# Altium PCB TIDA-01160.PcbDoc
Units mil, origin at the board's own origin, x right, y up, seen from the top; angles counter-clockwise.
Board outline 1299.21 x 905.51 mil, 2 copper layers (Top Layer, Bottom Layer), stack 62 mil thick; 52 components, 24 nets, 111 pads, 30 vias.
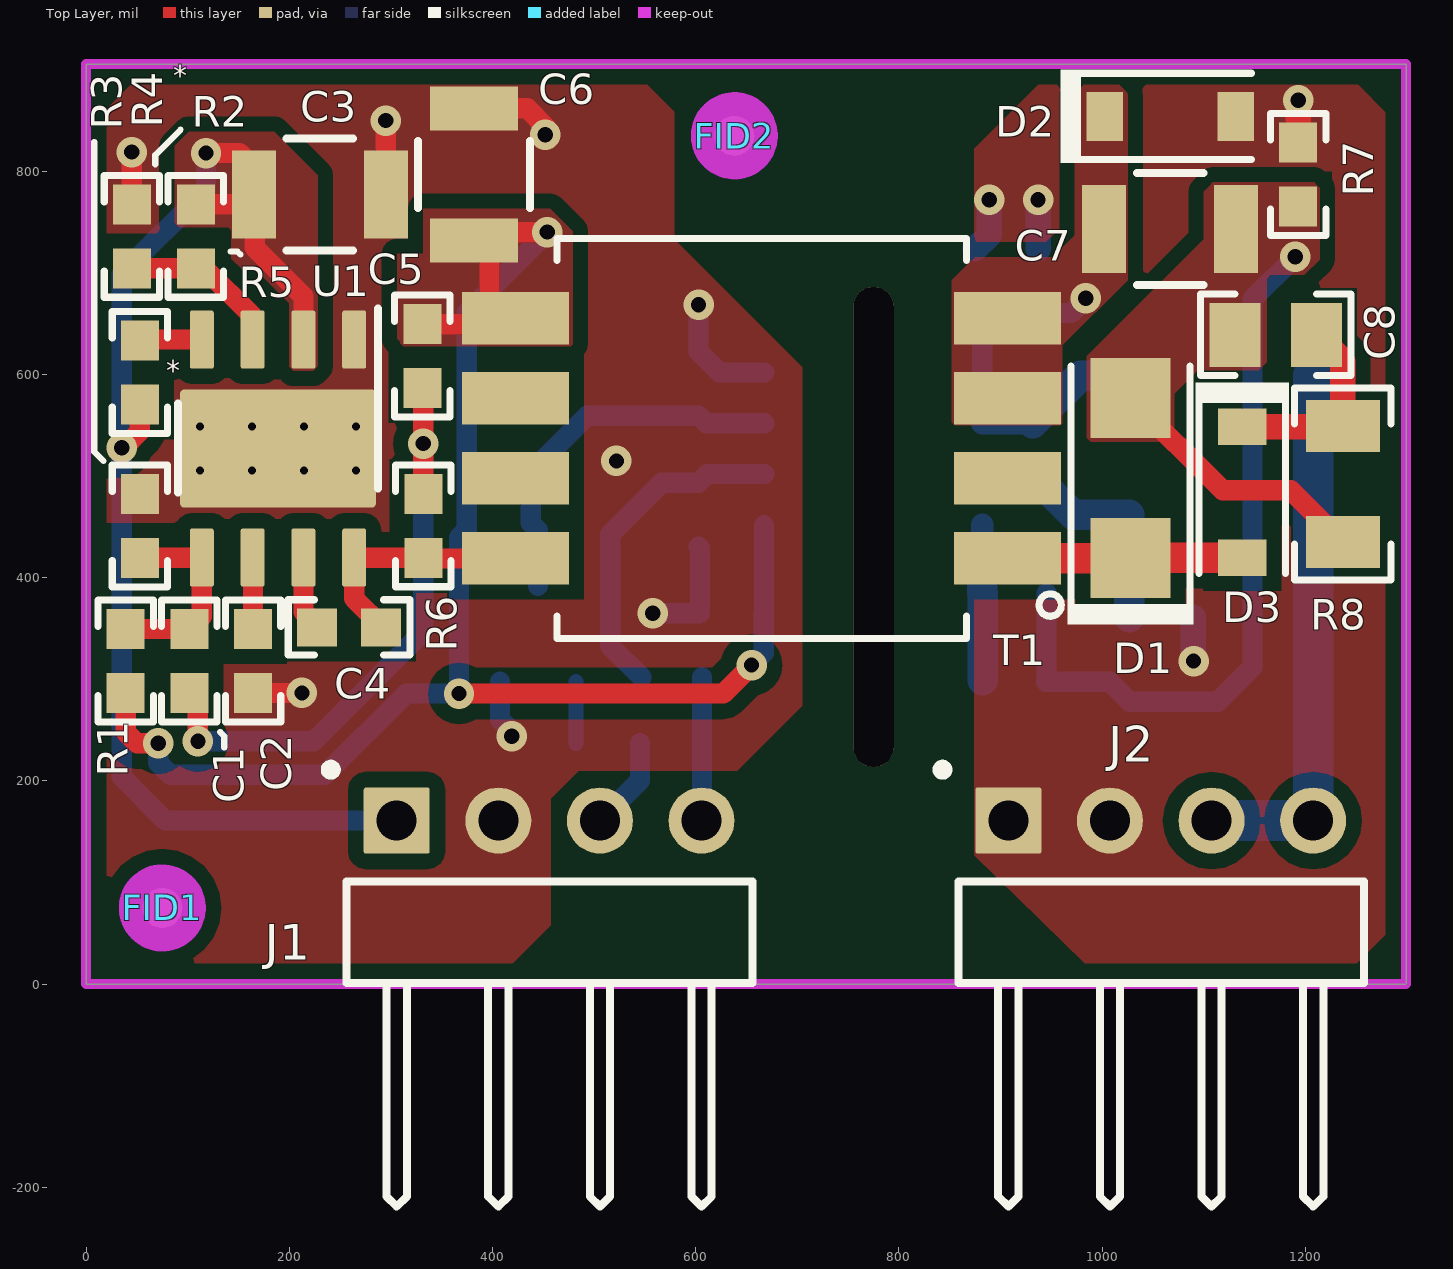
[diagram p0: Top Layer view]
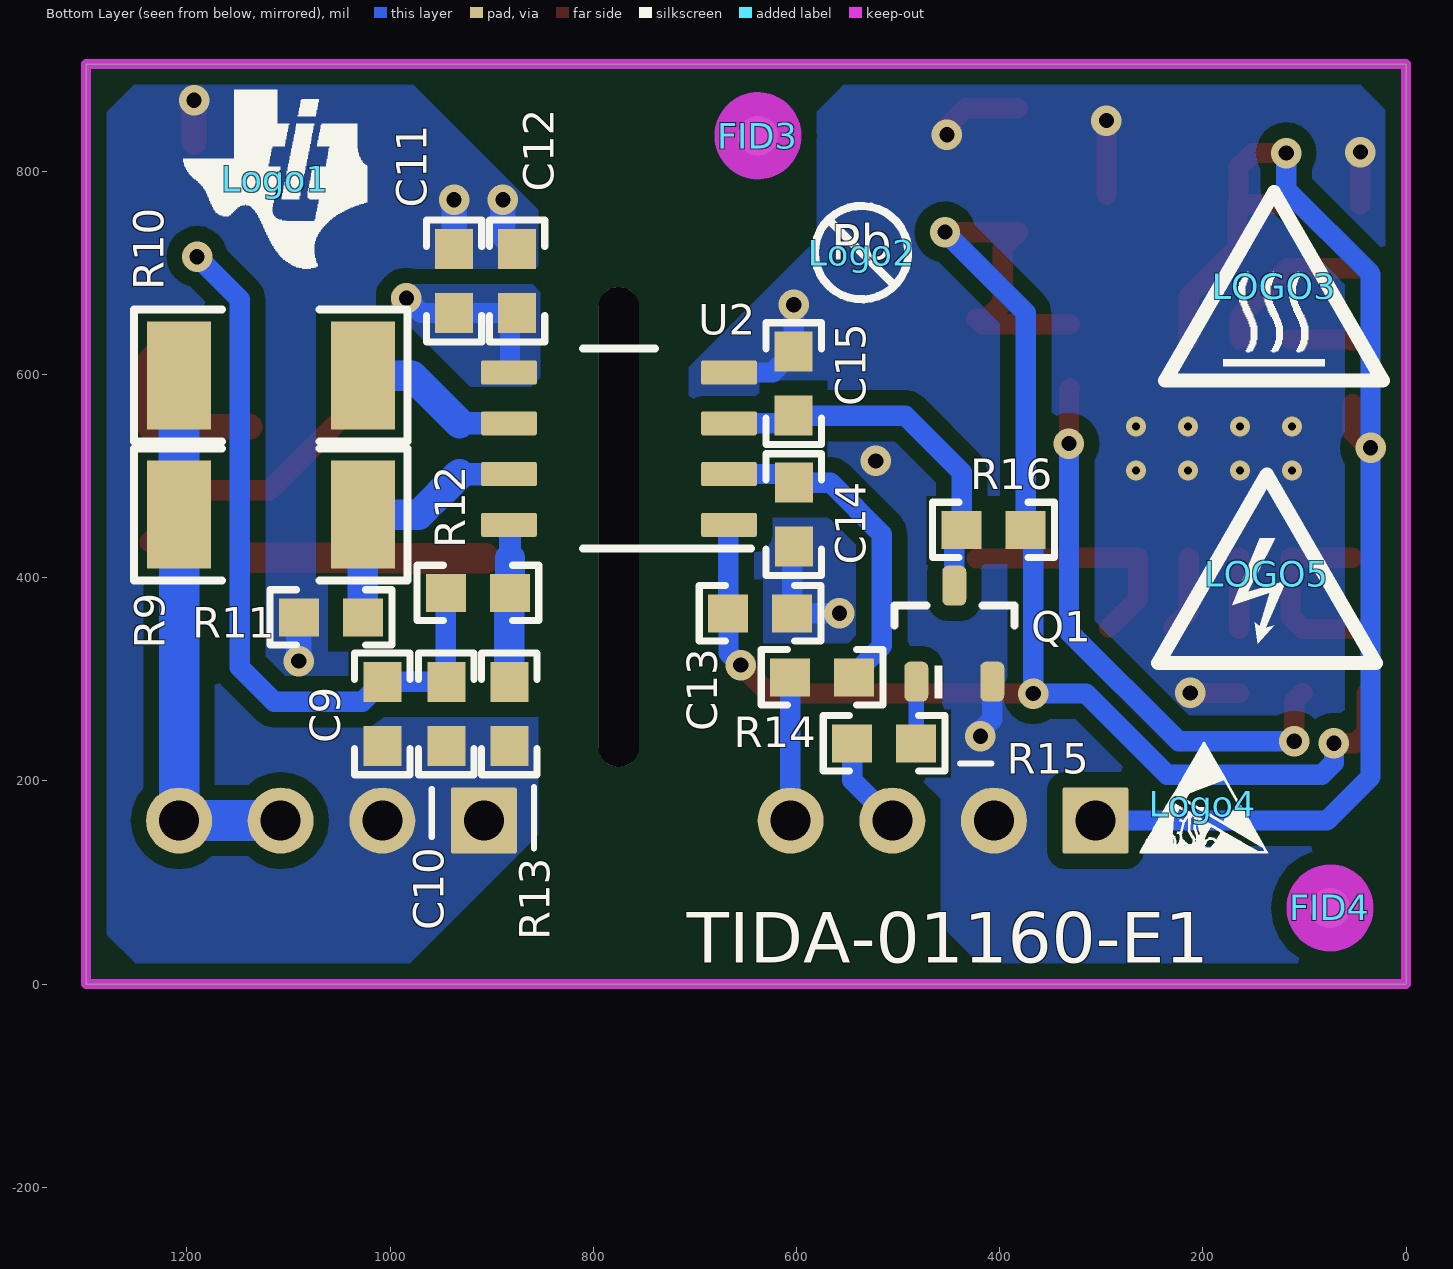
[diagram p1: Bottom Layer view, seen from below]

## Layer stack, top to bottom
Top Solder: solder mask 0.4, Solder Resist, Dk 3.5
Top Layer: signal copper 1.4
Dielectric1: core 59.2, FR-4 High Tg, Dk 4.8
Bottom Layer: signal copper 1.4
Bottom Solder: solder mask 0.4, Solder Resist, Dk 3.5

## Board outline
0,0 0,905.51 1299.21,905.51 1299.21,0

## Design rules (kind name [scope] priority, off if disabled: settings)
AcuteAngle [All] p1: minimum=4.50000000000000E+0001 checktracksonly=FALSE
AssemblyTestPointUsage [All] p1: valid=2
Clearance Clearance_Keepouts [((IsTrack Or IsArc) And Not InPoly) And IsFree and IsKeepOut vs ((IsTrack Or IsArc) And Not InPoly) And IsFree and IsKeepOut] p1: gap=15
Clearance Clearance_BoardEdge_MountingHoles [OnCopper and InComponentClass('Mounting Holes') vs IsKeepOut] p2: gap=40
Clearance Clearance_BoardEdge_Poly [OnCopper and InPoly vs IsKeepOut] p3: gap=15
Clearance Clearance_BoardEdge [OnCopper and Not InComponentClass('Logo') and not InComponentClass('FiducialMark') and not InRegion(1000,500,4000,800) and Not IsKeepout vs IsKeepOut] p4: gap=15
Clearance Clearance_Poly [InPolygon] p5: gap=15
Clearance [All] p6: gap=7.87
ComponentClearance ComponentClearance_MountingHoles_FiducialMarks [InComponentClass('Mounting Holes') vs InComponentClass('FiducialMark')] p1: gap=50 collisioncheckmode=3 verticalgap=10 showdistances=FALSE
ComponentClearance ComponentClearance_Shunt [InComponentClass('Header') vs InComponentClass('Shunt')] p2: gap=0 collisioncheckmode=3 verticalgap=0 showdistances=FALSE
ComponentClearance ComponentClearance_Logo [InComponentClass('Logo')] p3: gap=10 collisioncheckmode=3 verticalgap=10 showdistances=FALSE
ComponentClearance ComponentClearance_ScrewToNut [(HasFootprint('NY PMS 440 0025 PH')) vs (HasFootprint('Keystone_1902C'))] p4: gap=5 collisioncheckmode=3 verticalgap=10 showdistances=FALSE
ComponentClearance ComponentClearance_MountingHoles [InComponentClass('Mounting Holes')] p5: gap=200 collisioncheckmode=3 verticalgap=100000 showdistances=FALSE
ComponentClearance ComponentClearance_SmallPassives [HasFootprint('0201*') or HasFootprint('0402*') or HasFootprint('0508') or HasFootprint('0603*') or HasFootprint('0612') or HasFootprint('0805*') or HasFootprint('0815*') or HasFootprint('0830*') or HasFootprint('1206*') or HasFootprint('1210*') or HasFootprint('1808*') or HasFootprint('1812*') or HasFootprint('1825*') or HasFootprint('2010*') or HasFootprint('2220*') or HasFootprint('2225*') or HasFootprint('2512*') or HasFootprint('2728*') or HasFootprint('3518*') vs HasFootprint('0201*') or HasFootprint('0402*') or HasFootprint('0508') or HasFootprint('0603*') or HasFootprint('0612') or HasFootprint('0805*') or HasFootprint('0815*') or HasFootprint('0830*') or HasFootprint('1206*') or HasFootprint('1210*') or HasFootprint('1808*') or HasFootprint('1812*') or HasFootprint('1825*') or HasFootprint('2010*') or HasFootprint('2220*') or HasFootprint('2225*') or HasFootprint('2512*') or HasFootprint('2728*') or HasFootprint('3518*')] p6: gap=20 collisioncheckmode=3 verticalgap=10 showdistances=FALSE
ComponentClearance ComponentClearance_THtoSMT [IsThruComponent vs IsSMTComponent] p7: gap=20 collisioncheckmode=3 verticalgap=20 showdistances=FALSE
ComponentClearance ComponentClearance_THtoTH [IsThruComponent vs IsThruComponent] p8: gap=10 collisioncheckmode=3 verticalgap=10 showdistances=FALSE
ComponentClearance [All] p9: gap=20 collisioncheckmode=3 verticalgap=10 showdistances=FALSE
DiffPairsRouting [All] p1: maxlimit=100 minlimit=10 mostfreqgap=10 toplayer_minwidth=15 toplayer_maxwidth=15 toplayer_prefwidth=15 bottomlayer_minwidth=15 bottomlayer_maxwidth=15 bottomlayer_prefwidth=15 maxuncoupledlength=1000
FabricationTestPointUsage TestPointUsage [All] p1: valid=2 allowmultiple=FALSE
FabricationTestpoint Testpoint [All] p1: side=3 testpointundercomponent=TRUE minsize=40 maxsize=100 preferedsize=60 minholesize=0 maxholesize=40 preferedholesize=32 testpointgrid=1 allowsidetop=TRUE allowsidebottom=TRUE usegrid=TRUE gridtolerance=0.01
FanoutControl Fanout_LCC [IsLCC] p1: bgadir=Out bgaviamode=Centered fanoutstyle=Auto fanoutdirection=Alternating viagrid=1 // Fanout_LCC (Default Rule)
FanoutControl Fanout_BGA [IsBGA] p2: bgadir=Out bgaviamode=Centered fanoutstyle=Auto fanoutdirection=Alternating viagrid=1 // Fanout_BGA (Default Rule)
FanoutControl Fanout_Default [All] p4: bgadir=Out bgaviamode=Centered fanoutstyle=Auto fanoutdirection=Alternating viagrid=1 // Fanout_Default (Default Rule)
FanoutControl Fanout_Small [(CompPinCount < 5)] p5: bgadir=Out bgaviamode=Centered fanoutstyle=Auto fanoutdirection=OutThenIn viagrid=1 // Fanout_Small (Default Rule)
HoleSize [All] p1: absolutevalues=TRUE maxlimit=1000 minlimit=7.87 maxpercent=80.000 minpercent=20.000
MinimumAnnularRing MinimumAnnularRing_ThermalPadVias [IsVia and InAnyComponent] p1: minimumring=5.91
MinimumAnnularRing [All] p2: minimumring=6
MinimumSolderMaskSliver MinimumSolderMaskSliver_Logo [InComponentClass('Logo') vs InComponentClass('Logo')] p1: minsoldermaskwidth=0.7
MinimumSolderMaskSliver [All] p2: minsoldermaskwidth=3.94
PlaneConnect [All] p1: planeconnectstyle=Relief reliefexpansion=10 reliefentries=4 reliefconductorwidth=10 reliefairgap=10
PolygonConnect [All] p1: connectstyle=Direct reliefconductorwidth=10 reliefentries=4 polygonreliefangle="90 Angle" airgapwidth=10
RoutingVias ThermalPadVias [IsVia and InAnyComponent] p1: holewidth=7.87 width=19.68 viastyle="Through Hole" minholewidth=7.87 minwidth=19.68 maxholewidth=12.99 maxwidth=23.62
RoutingVias [All] p2: holewidth=12 width=24 viastyle="Through Hole" minholewidth=7.87 minwidth=26 maxholewidth=40 maxwidth=65
SilkToBoardRegionClearance [Not ((IsComment or IsDesignator) And (Hide <> 'False')) and not InRegion(1000,500,4000,800)] p1:
SilkToSilkClearance SilkToSilkClearance_Pb-FreeLogo [(HasFootprint('Pb-Free_Overlay_Medium') OR HasFootprint('Pb-Free_Overlay_Small')) vs (HasFootprint('Pb-Free_Overlay_Medium') OR HasFootprint('Pb-Free_Overlay_Small'))] p1: silktosilkclearance=0
SilkToSilkClearance [All] p2: silktosilkclearance=4
SilkToSolderMaskClearance "Silk to Solder Mask Opening" [All] p1: minsilkscreentomaskgap=4 clearancetoexposedcopper=FALSE
SolderMaskExpansion [All] p1: expansion=2.5
Width [All] p1: maxlimit=80 minlimit=6 preferedwidth=20 checkconnectedcopper=TRUE
15 further rules are at their usual default settings.

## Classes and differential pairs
component class TIDA-01160_Sheet1: C1 C2 C3 C4 C5 C6 C7 C8 C9 C10 C11 C12 C13 C14 C15 D1 D2 D3 J1 J2 Q1 R1 R2 R3 R4 R5 R6 R7 R8 R9 R10 R11 R12 R13 R14 R15 R16 T1 U1 U2
component class Logo: Logo1
component class TIDA-01160_Hardware: FID1 FID2 FID3 FID4 Logo1 Logo2 LOGO3 Logo4 LOGO5 ZZ1 ZZ2 ZZ3
component class FiducialMark: FID1 FID2 FID3 FID4
component class AssemblyNote: ZZ1 ZZ2 ZZ3

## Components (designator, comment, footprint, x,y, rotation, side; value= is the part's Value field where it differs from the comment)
C1 "C0603C103J5RACTU" 0603 101.64,318.11 r90 top
C2 "C0603C105K3RACTU" 0603 164.28,318.11 r270 top
C3 "C3225X7R1E106M250AC" 1210_280 230,777 r0 top
C4 "06035C104KAT2A" 0603 258.87,351.02 r0 top
C5 "C0603C222K5RACTU" 0603 330.87,618.11 r270 top
C6 "C3225X7R1E106M250AC" 1210_280 382,797 r270 top
C7 "C3225X7R1H106M250AC" 1210_280 1067,743 r0 top
C8 "GRM21BR72E103KW03L" 0805_HV 1170.87,639.11 r180 top
C9 "06035C104KAT2A" 0603 1007.72,266 r270 bottom
C10 "C1608X5R1H105K080AB" 0603 944.72,266 r270 bottom
C11 "C1608X5R1H105K080AB" 0603 937,692 r90 bottom
C12 "06035C104KAT2A" 0603 875,692 r90 bottom
C13 "06035C104KAT2A" 0603 635.72,365 r180 bottom
C14 "06035A101JAT2A" 0603 602.72,462 r90 bottom
C15 "06035A101JAT2A" 0603 602.78,591 r270 bottom
D1 "CDBA1150-HF" SMA 1027.87,498.11 r90 top
D2 "BZT52C15-7-F" SOD-123 1067,854 r0 top
D3 "CMHD4448 TR" SOD-123 1137.87,484.11 r270 top
FID1 "Fiducial" Fiducial10-20 75,75 r90 top
FID2 "Fiducial" Fiducial10-20 638,835 r90 top
FID3 "Fiducial" Fiducial10-20 638,835 r90 bottom
FID4 "Fiducial" Fiducial10-20 75,75 r90 bottom
J1 "TSW-104-08-G-S-RA" TSW-104-08-G-S-RA 455.72,161 r0 top
J2 "TSW-104-08-G-S-RA" TSW-104-08-G-S-RA 1057.72,161 r0 top
Logo1 "Texas Instruments" TI_Symbol_Overlay_Small 1113,792 r180 bottom
Logo2 "Pb-Free Symbol" Pb-Free_Overlay_Small 536,720 r180 bottom
LOGO3 "CAUTION HOT SURFACE" IEC_HotSurface_Small 130,687 r180 bottom
Logo4 "ESD Susceptible" ESD_Overlay_Small 200,177 r180 bottom
LOGO5 "DANGER HIGH VOLTAGE" IEC_HighVoltage_Small 137,404 r180 bottom
Q1 "2N7002" SOT-23 444.72,345 r90 bottom
R1 "RC0603FR-071K69L" 0603 38.87,318.02 r270 top
R2 "CRCW060317K4FKEA" 0603 45,736 r270 top
R3 "RC0603FR-071KL" 0603 52.87,451.02 r270 top
R4 "CRCW060373K2FKEA" 0603 52.94,602.11 r90 top
R5 "CRCW0603118KFKEA" 0603 108,736 r90 top
R6 "CRCW060349K9FKEA" 0603 331.87,451.11 r90 top
R7 "RC0603JR-0710KL" 0603 1193,797 r270 top
R8 "CRCW120668K1FKEA" 1206 1236.87,492.11 r90 top
R9 "CRCW20101R10JNEF" 2010 1117.27,462 r0 bottom
R10 "CRCW20101R10JNEF" 2010 1117.27,599 r0 bottom
R11 "CRCW06030000Z0EA" 0603 1058.27,361 r0 bottom
R12 "CRCW06030000Z0EA" 0603 913.72,385 r180 bottom
R13 "CRCW06030000Z0EA" 0603 882.72,266 r270 bottom
R14 "CRCW0603100RJNEA" 0603 574.72,302 r0 bottom
R15 "CRCW0603100RJNEA" 0603 513.72,237 r0 bottom
R16 "RC0603FR-07680RL" 0603 406,447 r180 bottom
T1 "750343468Rev02" WURTH_750315248 664.87,537.11 r180 top
U1 "LM25017MRX/NOPB" DDA0008B_N 188.87,527.11 r270 top
U2 "UCC5320SCD" D0008B_HV 774.72,527 r0 bottom
ZZ1 "These assemblies must comply with workmanship standards IPC-A-610 Class 2, unless otherwise specified." AssemblyNote 34,1942.49 r0 top
ZZ2 "These assemblies must be clean and free from flux and all contaminants. Use of no clean flux is not acceptable." AssemblyNote 34,2031.05 r0 top
ZZ3 "These assemblies are ESD sensitive, ESD precautions shall be observed." AssemblyNote 34,2119.6 r0 top

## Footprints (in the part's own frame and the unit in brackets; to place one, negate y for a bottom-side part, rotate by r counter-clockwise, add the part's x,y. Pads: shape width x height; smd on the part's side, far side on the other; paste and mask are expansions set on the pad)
0603 [mm] "0603 from SM-752 data"
  rect 1x0.95 smd: 1(-0.8,0) 2(0.8,0)
  silkscreen extent -1.52,-0.69 1.52,0.69, body extent -0.87,-0.47 0.87,0.47, height 1
0805_HV [mil] "0805 with 30mil clearance between pads"
  rect 50x63 smd: 1(-40,0) 2(40,0)
  silkscreen extent -74,-40 74,40, body extent -43,-29 43,29, height 57
1206 [mm] "1206 from SM-752 data"
  rect 1.3x1.85 smd: 1(-1.45,0) 2(1.45,0)
  silkscreen extent -2.4,-1.21 2.4,1.21, body extent -1.7,-0.9 1.7,0.9, height 1.35
1210_280 [mm] "SMD, 2-Leads, Body 3.6x2.8mm, Height 2.8mm"
  rect 1.1x2.2 smd: 1(-1.65,0) 2(1.65,0)
  silkscreen extent -0.84,-1.4 0.84,1.4, body extent -1.8,-1.4 1.8,1.4, height 2.8
2010 [mm] "Chip Capacitor, Body 5.08x2.54mm, IPC Medium Density"
  rect 1.6x2.7 smd: 1(-2.3,0) 2(2.3,0)
  silkscreen extent -3.42,-1.65 3.42,1.65, body extent -2.73,-1.45 2.73,1.45, height 1.66
AssemblyNote [mil] "Assembly Note"
D0008B_HV [mm] "SOIC, 8-Leads, Body 4.9x3.9mm, Pitch 1.27mm, HV / Isolation option"
  rrect17% 1.4x0.6 smd: 1(-2.75,1.905) 2(-2.75,0.635) 3(-2.75,-0.635) 4(-2.75,-1.905) 5(2.75,-1.905) 6(2.75,-0.635) 7(2.75,0.635) 8(2.75,1.905)
  silkscreen extent -3.3,-2.5 0.9,2.5, body extent -3,-2.45 3,2.45, height 1.63
DDA0008B_N [mm] "SOIC, 8-Leads, Body 4.9x3.9mm, Pitch 1.27mm, Exposed Pad, IPC Medium Density"
  rrect17% 1.45x0.6 smd: 1(-2.725,1.905) 2(-2.725,0.635) 3(-2.725,-0.635) 4(-2.725,-1.905) 5(2.725,-1.905) 6(2.725,-0.635) 7(2.725,0.635) 8(2.725,1.905)
  rrect7% 2.95x4.9 smd: 9(0,0)
  rrect4% 2.71x3.4 on Top Paste: 9(0,0)
  rrect4% 2.71x3.4 on Top Solder: 9(0,0)
  silkscreen extent -3.5,-2.5 1.1,2.5, body extent -3.01,-2.45 3.01,2.45, height 1.57
ESD_Overlay_Small [mil]
  silkscreen extent -62,-48 64,61
Fiducial10-20 [mm]
  round 1 smd mask+0.5: 1(0,0)
  Top Layer keep-out circle w1.178: c0,0 r0.5
IEC_HighVoltage_Small [mil]
  silkscreen extent -107,-88 107,97
IEC_HotSurface_Small [mil]
  silkscreen extent -107,-93 107,92
Pb-Free_Overlay_Small [mil]
  silkscreen extent -46,-46 46,46
SMA [mm] "Molded Diode, 2-Leads, Body 4.3x2.6mm, IPC Medium Density, based on OnSemi component dimensions and land pattern"
  rect 2x2 smd: 1(-2,0) 2(2,0)
  silkscreen extent -3.66,-1.57 2.79,1.57, body extent -2.6,-1.3 2.6,1.3, height 2.42
SOD-123 [mm] "On Semi recommended land pattern"
  rect 0.915x1.22 smd: 1(-1.637,0) 2(1.637,0)
  silkscreen extent -2.74,-1.17 2.03,1.17, body extent -1.93,-0.9 1.93,0.9, height 1.35
SOT-23 [mm] "SOT23, 3-Leads, Body 2.9x1.3mm, Pitch 0.95mm, Lead Span 2.5mm, IPC Medium Density"
  rrect50% 1x0.6 smd: 1(-1.2,0.95) 2(-1.2,-0.95) 3(1.2,0)
  silkscreen extent -1.62,-1.5 0.7,1.5, body extent -1.16,-1.45 1.21,1.45, height 1
TI_Symbol_Overlay_Small [mil]
  silkscreen extent -90,-88 91,88
TSW-104-08-G-S-RA [mm] "Samtec Right Angle Header"
  rrect6% 1.65x1.65 hole 1: 1(-3.81,0)
  round 1.65 hole 1: 2(-1.27,0) 3(1.27,0) 4(3.81,0)
  silkscreen extent -5.58,-9.65 5.08,1.39, body extent -5.08,-9.91 5.08,0.32, height 3.05
WURTH_750315248 [mm] "TRANSFORMER, SMD-8P"
  rect 2.67x1.31 smd: 1(-6.15,3) 2(-6.15,1) 3(-6.15,-1) 4(-6.15,-3) 5(6.15,-3) 6(6.15,-1) 7(6.15,1) 8(6.15,3)
  silkscreen extent -7.49,-5 5.12,5, body extent -5.12,-5 5.12,5, height 5

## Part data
C1: "CAP, CERM, 0.01 µF, 50 V, +/- 5%, X7R, 0603"
C2: "CAP, CERM, 1 µF, 25 V, +/- 10%, X7R, 0603"
C3 C6: "CAP, CERM, 10 µF, 25 V, +/- 20%, X7R, 1210"
C4 C9 C12 C13: "CAP, CERM, 0.1 µF, 50 V, +/- 10%, X7R, 0603"
C5: "CAP, CERM, 2200 pF, 50 V, +/- 10%, X7R, 0603"
C7: "CAP, CERM, 10 µF, 50 V, +/- 20%, X7R, 1210"
C8: "CAP, CERM, 0.01 µF, 250 V, +/- 10%, X7R, 0805"
C10 C11: "CAP, CERM, 1 µF, 50 V, +/- 10%, X5R, 0603"
C14 C15: "CAP, CERM, 100 pF, 50 V, +/- 5%, C0G/NP0, 0603"
D1: library part STPS1150A, "Diode, Schottky, 150 V, 1 A, Surface Mount DO-214AC, SMA"
D2: "Diode, Zener, 15 V, 370 mW, AEC-Q101, SOD-123"
D3: "Diode, Switching, 100 V, 0.25 A, SOD-123"
FID1 FID2 FID3 FID4: "Fiducial mark.  There is nothing to buy or mount."
J1 J2: "Header, 100mil, 4x1, Gold, R/A, TH"
Logo1: library part TI_Logo, "Texas Instrument Corporate Signature"
Logo2: library part Pb-Free
LOGO3: library part IEC_HotSurface, "IEC 61010-1 Hot Surface Warning"
Logo4: library part ESD_Susceptible, "ESD Susceptible Symbol"
LOGO5: library part IEC_HighVoltage, "IEC 61010-1 High Voltage Warning"
Q1: "MOSFET, N-CH, 60 V, 115 A, SOT-23"
R1: "RES, 1.69 k, 1%, 0.1 W, 0603"
R2: "RES, 17.4 k, 1%, 0.1 W, 0603"
R3: "RES, 1.00 k, 1%, 0.1 W, 0603"
R4: "RES, 73.2 k, 1%, 0.1 W, 0603"
R5: "RES, 118 k, 1%, 0.1 W, 0603"
R6: "RES, 49.9 k, 1%, 0.1 W, 0603"
R7: "RES, 10 k, 5%, 0.1 W, 0603"
R8: "RES, 68.1 k, 1%, 0.25 W, 1206"
R9 R10: "RES, 1.1, 5%, 0.75 W, AEC-Q200 Grade 0, 2010"
R11 R12 R13: "RES, 0, 5%, 0.1 W, 0603"
R14 R15: "RES, 100, 5%, 0.1 W, 0603"
R16: "RES, 680, 1%, 0.1 W, 0603"
T1: library part 760390015, "Transformer, 10µH, SMT"
U1: "48V, 650mA Constant On-Time Synchronous Buck Regulator, DDA0008B"
U2: "Isolated Gate Drivers with High CMTI and Scalable Drive Strength, D0008B (SOIC-8)"
ZZ1 ZZ2 ZZ3: library part AssemblyNote

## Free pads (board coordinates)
  oval 39.37x472.44 hole 39.37 slot 472.44 at 90 deg unplated mask+5: 0(775,450)

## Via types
v1: diameter 30, hole 15, Top Layer to Bottom Layer, 22 vias
v2: diameter 19.68, hole 7.87, Top Layer to Bottom Layer, 8 vias

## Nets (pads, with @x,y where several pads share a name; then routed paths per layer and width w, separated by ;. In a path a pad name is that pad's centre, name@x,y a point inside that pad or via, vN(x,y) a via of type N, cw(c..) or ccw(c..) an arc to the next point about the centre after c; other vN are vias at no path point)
+15V: C7.1 C11.1 C12.1 D2.1 T1.3 T1.4 U2.5 | length 166.9
  Bottom Layer w20: U2.5@882,602 882,660.22 881.72,660.5 C11.1 969.5,660.5 v1(984,675)
-8V: C7.2 C8.2 C9.1 C10.1 D1.2 R7.2 R8.1 R12.1 | length 1002.3
  Top Layer w20: D1.2 1118.72,486 1185.9,486 R8.1
  Bottom Layer w20: R12.1 945.21,297.99 C10.1 C9.1 1027.21,278 1114,278 1148,312 1148,674 v1(1190,716)
EN_PWM: J1.3 R15.2 | length 92.4
  Bottom Layer w20: J1.3 545.21,200.5 R15.2
GATE: J2.3 J2.4 R9.2 R10.2 | length 538
  Bottom Layer w40: J2.3 J2.4 1207.72,461.9 R9.2 R10.2
GND1: C2.2 C3.2 C6.1 C13.2 C14.1 C15.1 J1.2 Q1.2 R2.1 R3.1 U1.1 U1.9@188.87,527.11 U2.4 | length 548.7
  Top Layer w20: R2.1 v1(45,819) ; C2.2 v1(212.39,286.61) ; C3.2 v1(294.96,849.96) ; C6.1 434.04,861.96 452,844 v1(452,836)
  Bottom Layer w20: Q1.2 407.32,260.68 419,249 v1(419,244) ; v1(557.72,365) C13.2 604.22,429 C14.1 ; v1(602.78,668.78) C15.1 623.28,602 U2.4 U2.4@667.43,602
  other v1: 522,515
  other v2: 112.1,505.46 163.28,505.46 214.46,505.46 265.65,505.46 112.1,548.76 163.28,548.76 214.46,548.76 265.65,548.76
GND2: C9.2 C10.2 C11.2 C12.2 D2.2 J2.1 J2.2 R7.1 R11.2 R13.2 | length 186.3
  Top Layer w25: R7.1 v1(1193,870) v1@1193,872
  Bottom Layer w25: C12.2 889,737.5 v1(889,772) ; C11.2 v1(937,772) ; v1@1089.76,321 R11.2
  other v1: 1090,318
NetC1_1: C1.1 C5.2 R6.2 | length 607.2
  Top Layer w20: C1.1 110,278.26 v1(110,239) ; C5.2 331.87,585.61 v1(331.87,532) R6.2
  Bottom Layer w20: v1(110,239) 224,239 331.87,346.87 v1(331.87,532)
NetC1_2: C1.2 R1.1 R3.2 U1.5 | length 199.2
  Top Layer w20: R1.1 38.96,349.61 C1.2 113.87,361.84 U1.5 113.57,419.53 R3.2
NetC2_1: C2.1 U1.6 | length 70.4
  Top Layer w20: U1.6 164.28,419.42 C2.1
NetC4_1: C4.1 U1.7 | length 75.2
  Top Layer w20: U1.7 213.87,366.53 C4.1@229.38,351.02
NetC4_2: C4.2 R6.1 T1.8 U1.8 | length 239.8
  Top Layer w20: C4.2@292.37,351.02 263.87,379.52 U1.8 264.09,419.61 R6.1 332.49,419 T1.8
NetC8_1: C8.1 D3.1 R8.2 | length 199.9
  Top Layer w25: D3.1 1236.26,548.58 R8.2 1236.87,613.11 C8.1
NetC14_2: C14.2 R14.1 U2.2 | length 329.6
  Bottom Layer w20: R14.1@546.72,302 516,332.72 516,443 566.5,493.5 C14.2 611.22,502 U2.2 U2.2@667.43,502
NetC15_2: C15.2 Q1.3 R16.1 U2.3 | length 370.8
  Bottom Layer w20: Q1.3 444.72,446.78 437.5,454 437.5,504 493,559.5 C15.2 610.29,552 U2.3 U2.3@667.43,552
NetD1_1: D1.1 D3.2 T1.1 | length 231.1
  Top Layer w30: T1.1 1027.5,419 D1.1 1028.15,419.64 D3.2
NetQ1_1: Q1.1 R15.1 | length 60.8
  Bottom Layer w15: Q1.1 482.12,237.1 R15.1
NetR2_2: R2.2 R5.1 U1.3 | length 161.2
  Top Layer w20: R2.2 R5.1 116.5,704.5 163.87,657.13 U1.3
NetR4_2: R4.2 U1.4 | length 61.3
  Top Layer w20: R4.2 53.73,634.39 U1.4
NetR12_2: R12.2 R13.1 U2.8 | length 153.3
  Bottom Layer w22: 882,419.28 U2.8@882,452
  Bottom Layer w30: 882,419.28 882,385.22 R12.2 882.72,384.5 R13.1@882.72,299
OUTH: R10.1 U2.6 | length 164.2
  Bottom Layer w22: U2.6@882,552 U2.6 931.72,552
  Bottom Layer w30: 931.72,552 978.72,599 R10.1
OUTL: R9.1 R11.1 U2.7 | length 262.3
  Bottom Layer w22: U2.7@882,502 U2.7 931.72,502
  Bottom Layer w30: 931.72,502 971.72,462 R9.1 1026.77,461.94 R11.1
PWM: J1.4 R14.2 | length 141.2
  Bottom Layer w20: J1.4 606.21,161.5 R14.2
VCC1: C5.1 C6.2 C13.1 R1.2 R16.2 T1.5 U2.1 | length 1635.6
  Top Layer w20: R1.2 38.87,248.13 50,237 v1(71,237) ; C5.1 417.13,649.61 T1.5 411.78,655.22 397,670 397,725.02 381.87,740.15 v1(453.85,740.15) ; v1(367,286) 627,286 v1(655,314)
  Bottom Layer w15: U2.1@667.21,451.78 U2.1@667.43,452
  Bottom Layer w20: v1(71,237) 71,218 82.87,206.13 146.87,206.13 147,206 235,206 315,286 v1(367,286) 367,439.5 R16.2 374.5,660.8 v1(453.85,740.15) ; v1(655,314) 667,326 667,364.79 C13.1 U2.1@667.21,451.78
VCC/12V: C3.1 J1.1 R4.1 R5.2 U1.2 | length 1278.9
  Top Layer w20: v1(35,528) 37,528 52.94,543.94 R4.1 ; R5.2 166.04,767.5 166.04,724.96 213.87,677.13 U1.2 ; v1(118,818) 151,818 165.04,803.96 C3.1
  Bottom Layer w20: v1(118,818) 118,782 35,699 v1(35,528) 35,204 78,161 J1.1
pads on no net: FID1.1 FID2.1 FID3.1 FID4.1 T1.2 T1.6 T1.7 U1.9@188.87,527.11

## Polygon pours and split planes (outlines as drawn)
no net on Top Solder "M9 Title Sheet-No Net" (solid): 714.89,-0.08 833,-0.08 833,905.51 714.89,905.51
GND1 on Top Layer "Bottom Layer-No Net" (solid, remove dead copper, pour order 42): 0,182 0,52 52,0 399.49,0 457.24,57.76 457.24,182.24 485,210 641,210 705,274 705,607 579,733 579,858.51 532,905.51 406.49,905.51 64.51,905.51 0,841
VCC/12V on Top Layer "Bottom Layer-No Net" (solid, remove dead copper, pour order 26): 87,781 87,749 90,746 91,745 97,745 140,745 142,743 143,742 143,710 143,705 145,703 167,703 175,695 200,670 200,640 200,607.74 204,603.74 223.74,603.74 227,607 228,608 228,634 228,796 192,832 185,839 159,839 101,839 87,825
VCC1 on Top Layer "Bottom Layer-No Net" (solid, remove dead copper, pour order 24): 337,744 337,702 312,677 309,674 309,660 309,631 312,628 370,628 477,628 478,629 479,630 479,655 479,741 467,753 463,757 420,757 340,757 337,754
VCC1 on Top Layer "Bottom Layer-No Net" (solid, remove dead copper, pour order 0): 306,715 306,635 312,629 337,629 474,629 476,631 476,744 457,763 415,763 317,763 306,752
+15V on Top Layer "Bottom Layer-No Net" (solid, remove dead copper, pour order 2): 852,678 852,553 855,550 870,550 959,550 961,552 961,578 961,629 1025,693 1025,805 1025,877 1016,886 983,886 973,876 973,737 951.5,715.5 874.5,715.5 852,693
-8V on Top Layer "Bottom Layer-No Net" (solid, remove dead copper, pour order 6): 985,617 985,538 987,536 989,534 1015,534 1065,534 1071,540 1071,564 1071,581 1084,594 1094,604 1140,604 1154,604 1158,608 1162,612 1162,654 1162,672 1162,694 1166,698 1199,698 1214,713 1214,784 1211,787 1209,789 1148,789 1109,789 1106,786 1100,780 1100,735 1100,733 985,618
GND1 on Top Layer "Bottom Layer-No Net" (solid, remove dead copper, pour order 8): 32,502 81,502 87,508 90.45,511.45 90.45,555 90.45,573.45 95,578 97,580 125,580 245,580 250,585 251,586 251,609 251,661 254,664 274,664 277,661 279,659 279,603 279,485 272,478 265,471 40,471 32,479
GND2 on Top Layer "Bottom Layer-No Net" (solid, remove dead copper, pour order 22): 874,229.23 874,126.98 1004,0 1230,0 1300,70 1300,837 1231.49,905.51 957.51,905.51 874,822 874,726
no net on Bottom Solder "M9 Title Sheet-No Net" (solid): 714.89,-0.08 833,-0.08 833,905.51 714.89,905.51
GND2 on Bottom Layer "Bottom Layer-No Net" (solid, remove dead copper, pour order 40): 854,147 1001,0 1230,0 1300,70 1300,837 1231.49,905.51 997.51,905.51 854,762
+15V on Bottom Layer "Bottom Layer-No Net" (solid, remove dead copper, pour order 30): 852,675 852,597 858,591 861,588 893,588 921,588 994,661 999,666 999,679 999,680 990,689 975,689 860,689 852,681
GND1 on Bottom Layer "Bottom Layer-No Net" (solid, remove dead copper, pour order 44): 1,182 1,52 53,0 400.49,0 458.24,57.76 458.24,182.24 486,210 642,210 706,274 706,607 580,733 580,858.51 533,905.51 407.49,905.51 65.51,905.51 1,841

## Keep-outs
Keep-Out Layer:
  the board outline again, w10
  text ".Layer_Name" at 481,-1164 h60

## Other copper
Top Layer:
  text ".Layer_Name" at 481,-1164 h60
Bottom Layer:
  text ".Layer_Name" at 481,-1164 h60

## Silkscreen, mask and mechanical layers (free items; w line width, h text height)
Top Overlay:
  lines w6: 8,829 8,524 17,515 ; 68,807 68,816 93,841 ; 132,248 136,244 136,233 ; 142,721 149,721 152,718
  text "*" at 86,884 h20
  text "*" at 79,594 h20
  text ".Layer_Name" at 481,-1164 h60
Bottom Overlay:
  lines w6: 408,217 439,217 ; 858.5,133.5 858.5,194 ; 959,145 959,192
  text "TIDA-01160-E1" at 708,21 h50
  text ".Layer_Name" at 481,-1164 h60
Top Paste:
  text ".Layer_Name" at 481,-1164 h60
Bottom Paste:
  text ".Layer_Name" at 481,-1164 h60
Top Solder:
  text ".Layer_Name" at 481,-1164 h60
  text ".Layer_Name" at 481,-1164 h60
Bottom Solder:
  text ".Layer_Name" at 481,-1164 h60
Drill Guide:
  text ".Layer_Name" at 481,-1164 h60
M1 Board Outline:
  the board outline again, w10
  text ".Layer_Name" at 455,-1156 h60
M2 Board Dimensions:
  rectangle: -96,-580.51 29,-455.51
  rectangle: 29,-705.51 404,-580.51
  lines w7: -96,-580.51 904,-580.51 ; 29,-705.51 29,-455.51 ; 154,-705.51 154,-455.51 ; 404,-705.51 404,-455.51 ; 654,-705.51 654,-455.51 ; -96,-705.51 904,-705.51 904,-455.51 -96,-455.51 -96,-705.51
M3 3D STEP Top:
  text ".Layer_Name" at 481,-1164 h60
M4 3D STEP Bottom:
  text ".Layer_Name" at 481,-1164 h60
M5 Assembly Top:
  circle w10: c901,162 r9.06
  circle w10: c306,163 r10
  lines w10: -388,-1235.68 6212,-1235.68 ; -388,-1032.34 6214,-1032.34 ; -388,-829.01 -388,-1439.01 3617,-1439.01 6214,-1439.01 6214,-829.01 -387.5,-829.01 -387.5,-1439.01 1188,-1439.01 ; 2077,-1439.01 2077,-829.01 ; 3344,-1032.34 3344,-829.01 ; 4184,-1032.34 4184,-829.01 ; 4806,-1445.51 4806,-1242.68
  text "COMPONENTS MARKED 'DNP' SHOULD NOT BE POPULATED." at 1057.5,-624.01 h60
  text "ASSEMBLY VARIANT:" at 1057,-739.51 h60
  text ".VariantName" at 2093,-739.51 h60
  text "PCB VIEWED FROM TOP SIDE" at -324.5,-961.18 h60
  text "BOARD #:" at 2152,-961.18 h60
  text ".PRJ_Number" at 2697.5,-961.18 h60
  text "REV:" at 3542,-961.18 h60
  text ".PCB_Rev" at 3833.5,-961.18 h60
  text "SVN REV:" at 4380,-961.18 h60
  text ".VersionControl_RevNumber" at 4886,-961.18 h60
  text ".LAyer_Name" at 451,-1161 h60
  text "LAYER NAME =" at -324.5,-1164 h60
  text "TID #:" at 2152,-1164.51 h60
  text ".TID" at 2697.5,-1164.51 h60
  text "PLOT NAME =" at -324.5,-1369.85 h60
  text ".plot_File_Name" at 481,-1369.85 h60
  text "GENERATED    :" at 2154,-1369.85 h60
  text ".Print_Date" at 3023.5,-1369.85 h60
  text ".Print_Time" at 3752.5,-1369.85 h60
  text "TEXAS INSTRUMENTS" at 5017,-1369.85 h60
M6 Assembly Bottom:
  circle w10: c481,284 r2
  lines w10: -388.5,-1032.84 6213.5,-1032.84 ; -386.5,-1236.18 6213.5,-1236.18 ; 1019.5,-1446.01 1019.5,-1243.18 ; 1641.5,-1032.84 1641.5,-829.51 ; 2481.5,-1032.84 2481.5,-829.51 ; 3748.5,-1439.51 3748.5,-829.51 ; 4637.5,-1439.51 6213,-1439.51 6213,-829.51 -388.5,-829.51 -388.5,-1439.51 2208.5,-1439.51 6213.5,-1439.51 6213.5,-829.51
  text "COMPONENTS MARKED 'DNP' SHOULD NOT BE POPULATED." at 6006,-623.51 h60
  text ".VariantName" at 4962,-739.51 h60
  text "ASSEMBLY VARIANT:" at 6001,-739.51 h60
  text ".VersionControl_RevNumber" at 939.5,-961.68 h60
  text "SVN REV:" at 1445.5,-961.68 h60
  text ".PCB_Rev" at 1992,-961.68 h60
  text "REV:" at 2283.5,-961.68 h60
  text ".PRJ_Number" at 3128,-961.68 h60
  text "BOARD #:" at 3673.5,-961.68 h60
  text "PCB VIEWED FROM BOTTOM SIDE" at 6150,-961.68 h60
  text ".TID" at 3128,-1165.01 h60
  text "TID #:" at 3673.5,-1165.01 h60
  text ".LAyer_Name" at 5400,-1169 h60
  text "LAYER NAME =" at 6151,-1172 h60
  text "TEXAS INSTRUMENTS" at 808.5,-1370.35 h60
  text ".Print_Time" at 2073,-1370.35 h60
  text ".Print_Date" at 2802,-1370.35 h60
  text "GENERATED    :" at 3671.5,-1370.35 h60
  text ".plot_File_Name" at 5344.5,-1370.35 h60
  text "PLOT NAME =" at 6150,-1370.35 h60
M9 Title Sheet:
  drawing of 57 lines, arcs and shapes, not listed
  text "1" at 643.84,7730.99 h70
  text "2" at 3139.5,7730.99 h70
  text "3" at 5628.84,7730.99 h70
  text "4" at 8135.51,7730.99 h70
  text "5" at 10634.5,7730.99 h70
  text "6" at 13139.5,7730.99 h70
  text "A" at -512.5,6587.99 h70
  text "A" at 14287.5,6587.99 h70
  text "B" at -512.5,4207.99 h70
  text "B" at 14287.5,4207.99 h70
  text "C" at -512.5,1832.99 h70
  text "C" at 14287.5,1832.99 h70
  text "PROJECT TITLE:" at 11247.5,-28.01 h45
  text ".PRJ_Title" at 11297.5,-161.34 h70
  text "DESIGNED FOR:" at 11247.5,-329.01 h45
  text ".PRJ_Customer" at 11297.5,-469.01 h70
  text "D" at -512.5,-537.01 h70
  text "D" at 14287.5,-537.01 h70
  text "FILE NAME:" at 11247.5,-629.01 h45
  text ".PCB_File_Name_No_Path" at 11297.5,-749.01 h70
  text "Texas Instruments (TI) and/or its licensors do not warrant the accuracy or completeness of this specification" at 6278,-910.85 h45
  text "ENGINEER:" at 11247.5,-919.01 h45
  text "LAYOUT BY:" at 12752.5,-919.01 h45
  text "or any information contained therein. TI and/or its licensors do not warrant that this design will meet" at 6233.02,-1023.52 h45
  text ".PRJ_Engineer" at 11297.5,-1074 h70
  text ".PCB_Layout" at 12803,-1074 h70
  text "the specifications, will be suitable for your application or fit for any particular purpose, or will operate in" at 6233.02,-1136.18 h45
  text "ALTIUM DESIGNER VERSION:" at 12752.5,-1229.01 h45
  text "an implementation. TI and/or its licensors do not warrant that the design is production worthy. You should" at 6233.02,-1248.85 h45
  text "completely validate and test your design implementation to confirm the system functionality for your application." at 6278,-1361.51 h45
  text ".print_Scale" at 11297.5,-1362.34 h70
  text ".Application_BuildNumber" at 12803,-1362.34 h70
  text "1" at 643.84,-1569.01 h70
  text "2" at 3139.5,-1569.01 h70
  text "3" at 5628.84,-1569.01 h70
  text "4" at 8135.51,-1569.01 h70
  text "5" at 10634.5,-1569.01 h70
  text "6" at 13139.5,-1569.01 h70
M10 Fab Notes:
  drawing of 191 lines, arcs and shapes, not listed
  text "DESIGN INFORMATION" at 12290.52,6384.49 h60
  text "(REFER ALSO ARRAY/PANEL PROFILING INFORMATION)" at 11928.96,6222.77 h60
  text "BOARD SIZE" at 11242.96,6218.49 h60
  text "X" at 12210.96,6090.67 h60
  text "23MM" at 12446.5,6083.49 h60
  text "33MM" at 11697,6080 h60
  text "Number of Layers :" at 11660.96,5983.49 h60
  text "2" at 12755.77,5973.49 h60
  text "MIN. TRACK WIDTH:" at 11660.96,5844.49 h60
  text "15" at 12730.5,5844.89 h60
  text "MIL" at 12911.96,5844.49 h60
  text "MIN. CLEARANCE:" at 11660.96,5712.49 h60
  text "7.87" at 12679,5712 h60
  text "MIL" at 12929.5,5685.89 h60
  text "19.685" at 12572,5581 h60
  text "MIN. VIA PAD SIZE:" at 11660.96,5580.49 h60
  text "MIL" at 12929.5,5557.89 h60
  text "0.19mm (7.5MIL)" at 12355.96,5438.78 h60
  text "EXTERNAL" at 13092.5,5438.89 h60
  text "MINIMUM ANNULAR RING" at 11331.73,5434.49 h60
  text "PER" at 11531.73,5316.49 h60
  text "IPC-D-275 CLASS 2 LEVEL C" at 11751.73,5316.49 h60
  text "MIL, HOLES" at 13200.96,5182.2 h60
  text "+/-" at 12808.5,5181.49 h60
  text "+/-" at 13662.5,5181.49 h60
  text "REGISTRATION TOLERANCES:" at 11292.73,5176.49 h60
  text "METAL" at 12492.5,5176.49 h60
  text "5" at 13068.7,5176.49 h60
  text "3" at 13901.7,5176.49 h60
  text "MIL" at 14017.96,5176.49 h60
  text "HOLE SIZE TOLERANCE (UNLESS OTHERWISE SPECIFIED): +/- 3MIL" at 11281.73,5033.49 h60
  text "MATERIAL:" at 11240.96,4826.03 h60
  text "FR-4 High Tg" at 12227.4,4685.7 h60
  text "FR-408" at 11661.96,4677.13 h60
  text "OTHER" at 13149.96,4677.13 h60
  text "X" at 12065.5,4675.49 h60
  text "THICKNESS:" at 11242.5,4520.49 h60
  text "63 MIL (1.6mm) +/-10%" at 11901.5,4515.49 h60
  text "OTHER" at 13266.96,4510.13 h60
  text "X" at 11766.5,4507.49 h60
  text "TOLERANCE:" at 11315.73,4352.13 h60
  text "X" at 12155.03,4352.13 h60
  text "ANSI IPC-6012 TYPE 3 CLASS 2" at 12341.98,4352.13 h60
  text "OTHER +/-" at 12341.96,4196.13 h60
  text "BOW & TWIST:" at 11315.73,4039.13 h60
  text "X" at 12155.03,4039.13 h60
  text "ANSI IPC-6012 TYPE 3 CLASS 2" at 12341.98,4039.13 h60
  text "OTHER +/-" at 12341.96,3880.62 h60
  text "DRILLING:" at 11240.96,3742.13 h60
  text "REFERENCE:" at 11315.73,3625.13 h60
  text "X" at 11963.96,3625.13 h60
  text "AS SHOWN" at 12150.96,3625.13 h60
  text "X" at 12864.96,3625.13 h60
  text "NC_DRILL FILES" at 13001.96,3625.13 h60
  text "PTH MIN COPPER THICKNESS:" at 11315.73,3467.13 h60
  text "X" at 12665.96,3467.13 h60
  text "1MIL" at 12802.96,3467.13 h60
  text "OTHER" at 13299.96,3467.13 h60
  text "BOARD FINISH:" at 11240.96,3308.13 h60
  text "X" at 12349.92,3196.13 h60
  text "SILKSCREEN:" at 11396.18,3190.13 h60
  text "TOP" at 12470.96,3190.13 h60
  text "X" at 12854.96,3190.13 h60
  text "BOTTOM" at 12981.96,3190.13 h60
  text "SILKSCREEN COLOR:" at 11396.18,3023.13 h60
  text "X" at 12343.92,3023.13 h60
  text "WHITE" at 12470.96,3023.13 h60
  text "OTHER" at 12981.96,3023.13 h60
  text "SOLDER RESIST COLOR:" at 11396.18,2853.13 h60
  text "X" at 11963.92,2693.93 h60
  text "GREEN" at 12090.96,2693.93 h60
  text "BLUE" at 12681.96,2693.93 h60
  text "OTHER" at 13219.96,2693.93 h60
  text "IMMERSION GOLD (ENIG)" at 12301.96,2505.41 h60
  text "ENEPIG" at 13639.5,2502.13 h60
  text "SURFACE FINISH:" at 11240.96,2501.13 h60
  text "X" at 12115.01,2501.13 h60
  text "IMM. TIN/SILVER OR EQUIV" at 11570.5,2344.13 h60
  text "OTHER" at 13001.96,2344.13 h60
  text "ARRAY/PANEL:" at 11240.96,2165.13 h60
  text "CUT AND TRIM PER MECH LAYER 1" at 12301.96,2160.84 h60
  text "N.C. ROUTE" at 12301.96,2009.13 h60
  text "X" at 12980.96,2009.13 h60
  text "V. SCORE" at 13167.96,2009.13 h60
  text "CERTIFICATION:" at 11240.96,1872.13 h60
  text "MATERIALS AND WORKMANSHIP FOR ALL PCBS" at 11965.96,1872.13 h60
  text "TO MEET OR EXCEED THE REQUIREMENTS OF:" at 11965.96,1774.13 h60
  text "X" at 11592.46,1637.62 h60
  text "ANSI IPC-A-600F CLASS ->" at 11731.46,1637.62 h60
  text "X" at 13370.52,1637.62 h60
  text "2" at 13489.46,1637.62 h60
  text "1" at 13174.46,1636.13 h60
  text "3" at 13843.46,1636.13 h60
  text "X" at 11594.52,1478.13 h60
  text "UL 94V-0" at 11731.46,1478.13 h60
  text "X" at 12406.52,1478.13 h60
  text "RoHS" at 12543.46,1478.13 h60
  text "OTHER" at 13187.86,1478.13 h60
  text "PER ORDER" at 13584.92,1478.13 h60
  text "ADDITIONAL REQUIREMENTS:" at 11240.96,1337.13 h60
  text "MICROSECTION:" at 11315.73,1222.13 h60
  text "YES" at 12221.46,1222.13 h60
  text "REQUIRED" at 13082.96,1065.98 h60
  text "BARE BOARD ELEC. TEST:" at 11315.73,1063.13 h60
  text "NONE" at 12621.46,1063.13 h60
  text "X" at 12955.96,1063.13 h60
  text "PER ORDER" at 13674.96,1063.13 h60
  text "MANUFACTURER'S UL:" at 11315.73,906.13 h60
  text "RAIL" at 12481.46,901.84 h60
  text "METAL" at 12973.27,901.84 h60
  text "X" at 13348.5,901.49 h60
  text "SILK" at 13484.96,901.84 h60
  text "VIA`S TO BE TENTED:" at 11295.5,714.49 h60
  text "NO" at 12200.5,714.49 h60
  text "THIS IS NOT AN IMPEDANCE CONTROL BOARD" at 2408,-294 h60
M11 Gerber Information:
  lines w10: -388,-1235.68 6212,-1235.68 ; -388,-1032.34 6214,-1032.34 ; -388,-829.01 -388,-1439.01 3617,-1439.01 6214,-1439.01 6214,-829.01 -387.5,-829.01 -387.5,-1439.01 1188,-1439.01 ; 2077,-1439.01 2077,-829.01 ; 3344,-1032.34 3344,-829.01 ; 4184,-1032.34 4184,-829.01 ; 4806,-1445.51 4806,-1242.68
  text "ALL ARTWORK VIEWED FROM TOP SIDE" at -324.5,-961.18 h60
  text "BOARD #:" at 2152,-961.18 h60
  text ".PRJ_Number" at 2697.5,-961.18 h60
  text "REV:" at 3542,-961.18 h60
  text ".PCB_Rev" at 3833.5,-961.18 h60
  text "SVN REV:" at 4380,-961.18 h60
  text ".VersionControl_RevNumber" at 4886,-961.18 h60
  text "LAYER NAME =" at -324.5,-1164 h60
  text "TID #:" at 2152,-1164.51 h60
  text ".TID" at 2697.5,-1164.51 h60
  text "PLOT NAME =" at -324.5,-1369.85 h60
  text ".plot_File_Name" at 481,-1369.85 h60
  text "GENERATED    :" at 2154,-1369.85 h60
  text ".Print_Date" at 3023.5,-1369.85 h60
  text ".Print_Time" at 3752.5,-1369.85 h60
  text "TEXAS INSTRUMENTS" at 5017,-1369.85 h60
M12 Stackup:
  drawing of 191 lines, arcs and shapes, not listed
  text "Layer" at 9646,7459 h60
  text "Name" at 10055.91,7459 h60
  text "Material" at 10985.66,7459 h60
  text "Thickness" at 11845.42,7459 h60
  text "Constant" at 12495.26,7459 h60
  text "Board Layer Stack" at 13065.12,7459 h60
  text "1" at 9646,7339 h60
  text "Top Overlay" at 10055.91,7339 h60
  text "2" at 9646,7219 h60
  text "Top Solder" at 10055.91,7219 h60
  text "Solder Resist" at 10985.66,7219 h60
  text "0.40mil" at 11845.42,7219 h60
  text "3.5" at 12495.26,7219 h60
  text "3" at 9646,7099 h60
  text "Top Layer" at 10055.91,7099 h60
  text "Copper" at 10985.66,7099 h60
  text "1.40mil" at 11845.42,7099 h60
  text "4" at 9646,6979 h60
  text "Dielectric1" at 10055.91,6979 h60
  text "FR-4 High Tg" at 10985.66,6979 h60
  text "59.20mil" at 11845.42,6979 h60
  text "4.8" at 12495.26,6979 h60
  text "5" at 9646,6859 h60
  text "Bottom Layer" at 10055.91,6859 h60
  text "Copper" at 10985.66,6859 h60
  text "1.40mil" at 11845.42,6859 h60
  text "6" at 9646,6739 h60
  text "Bottom Solder" at 10055.91,6739 h60
  text "Solder Resist" at 10985.66,6739 h60
  text "0.40mil" at 11845.42,6739 h60
  text "3.5" at 12495.26,6739 h60
  text "7" at 9646,6619 h60
  text "Bottom Overlay" at 10055.91,6619 h60
M13 Component Bodies Top:
  text ".Layer_Name" at 481,-1164 h60
M14 Component Bodies Bottom:
  text ".Layer_Name" at 481,-1164 h60
M15 Courtyards Top:
  text ".Layer_Name" at 481,-1164 h60
M16 Courtyards Bottom:
  text ".Layer_Name" at 481,-1164 h60
Drill Drawing:
  circle w1: c1835.62,1264.94 r25
  lines w1: 1810.62,952.44 1823.12,952.44 1835.62,939.94 1848.12,952.44 1860.62,952.44 1848.12,964.94 1860.62,977.44 1848.12,977.44 1835.62,989.94 1823.12,977.44 1810.62,977.44 1823.12,964.94 1810.62,952.44 ; 1810.62,1089.94 1810.62,1102.44 1823.12,1114.94 1810.62,1127.44 1810.62,1139.94 1823.12,1139.94 1835.62,1127.44 1848.12,1139.94 1860.62,1139.94 1860.62,1127.44 1848.12,1114.94 1860.62,1102.44 1860.62,1089.94 1848.12,1089.94 1835.62,1102.44 1823.12,1089.94 1810.62,1089.94 ; 1810.62,1414.94 1835.62,1389.94 1860.62,1414.94 1835.62,1439.94 1810.62,1414.94
  lines w15: 1742.5,894.94 8044.76,894.94 ; 1742.5,1494.94 8044.76,1494.94 ; 2293.38,744.94 2293.38,1644.94 ; 2991.19,744.94 2991.19,1644.94 ; 4336.79,744.94 4336.79,1644.94 ; 4842.67,744.94 4842.67,1644.94 ; 5576.47,744.94 5576.47,1644.94 ; 6786.12,744.94 6786.12,1644.94 ; 1742.5,744.94 8044.76,744.94 8044.76,1644.94 1742.5,1644.94 1742.5,744.94
  text "Symbol" at 1832.5,1539.94 h72
  text "Hit Count" at 2338.38,1539.94 h72
  text "Finished Hole Size" at 3036.19,1539.94 h72
  text "Plated" at 4381.79,1539.94 h72
  text "Hole Type" at 4887.67,1539.94 h72
  text "Physical Length" at 5621.47,1539.94 h72
  text "Rout Path Length" at 6831.12,1539.94 h72
  text "1" at 2338.38,1389.94 h60
  text "39.37mil (1.000mm)" at 3036.19,1389.94 h60
  text "NPTH" at 4381.79,1389.94 h60
  text "Slot" at 4887.67,1389.94 h60
  text "472.44mil (12.000mm)" at 5621.47,1389.94 h60
  text "433.07mil (11.000mm)" at 6831.12,1389.94 h60
  text "8" at 2338.38,1239.94 h60
  text "7.87mil (0.200mm)" at 3036.19,1239.94 h60
  text "PTH" at 4381.79,1239.94 h60
  text "Round" at 4887.67,1239.94 h60
  text "8" at 2338.38,1089.94 h60
  text "39.37mil (1.000mm)" at 3036.19,1089.94 h60
  text "PTH" at 4381.79,1089.94 h60
  text "Round" at 4887.67,1089.94 h60
  text "22" at 2338.38,939.94 h60
  text "15.00mil (0.381mm)" at 3036.19,939.94 h60
  text "PTH" at 4381.79,939.94 h60
  text "Round" at 4887.67,939.94 h60
  text "39 Total" at 2338.38,789.94 h60
  text "Slot definitions :" at 1832.5,644.97 h60
  text "Rout Path Length" at 2865.19,644.97 h60
  text "= Calculated from tool start centre position to tool end centre position." at 3847.9,644.97 h60
  text "Physical Length" at 2865.19,544.99 h60
  text "= Rout Path Length + Tool Size = Slot length as defined in the PCB layout" at 3787.91,544.99 h60
  text "DRILL TABLE" at 2412,286 h60
  text "FOR PTH +3/-3MIL" at 2408,161 h60
  text "FOR NPTH +2/-2MIL" at 2405,52 h60
  text "FOR 15MIL PTH +0/-15MIL" at 2408,-64 h60
  text "FOR 7.87MIL PTH +0/-7.87MIL" at 2404,-169 h60
  text ".Layer_Name" at 481,-1164 h60

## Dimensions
0,905.51 to 1299.21,905.51 on M2 Board Dimensions
0,0 to 0,905.51 on M2 Board Dimensions
-96,-705.51 to 904,-705.51 on M2 Board Dimensions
